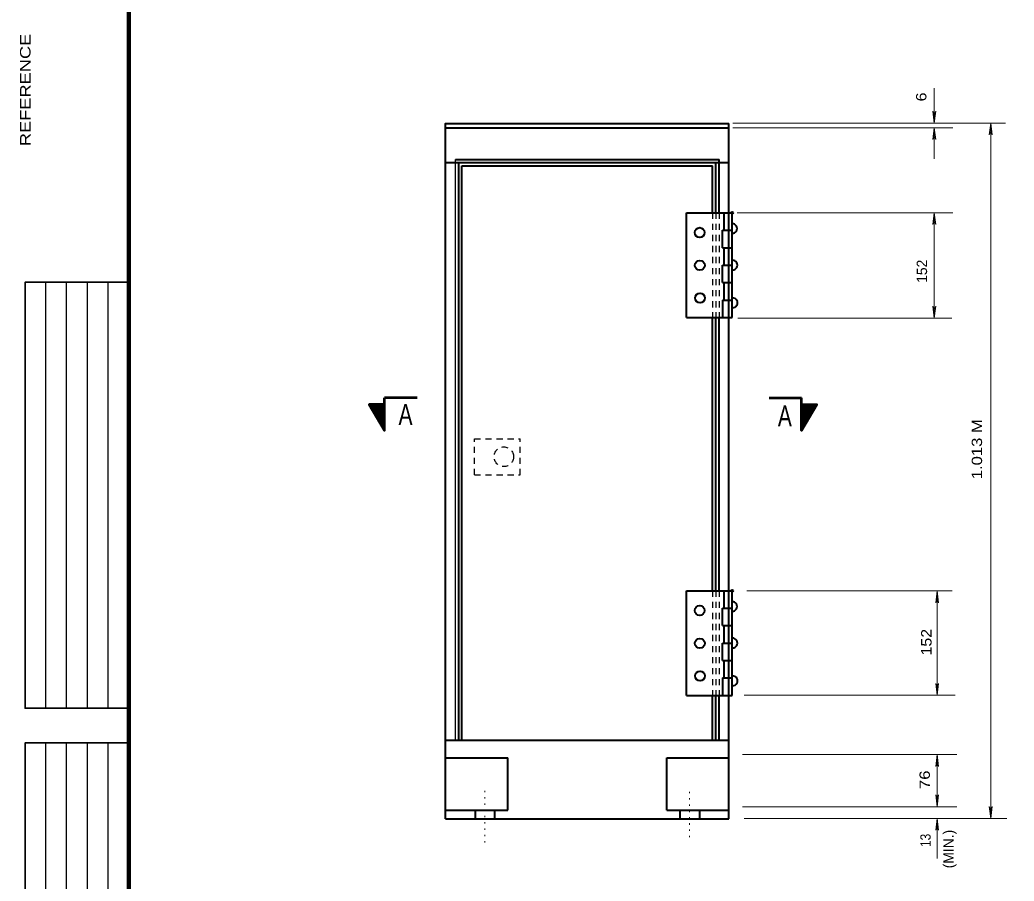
# Model space of a CAD drawing. Extents: x 312583 to 312853, y 144420 to 144585.
# Drawn here: x 312608.5 to 312681.4, y 144478 to 144541.1 of the extents above; entities that cross this region are included whole.
import ezdxf
from ezdxf.enums import TextEntityAlignment as Align

# ---------------------------------------------------------------- set-up
doc = ezdxf.new("R2010")
doc.units = 0
doc.header["$LTSCALE"] = 0.3
doc.header["$PDMODE"] = 32
doc.header["$PDSIZE"] = 0.15
doc.linetypes.add('DOTTED', pattern=[1.5, 0.3, -1.2])
doc.linetypes.add('SHORT_DASHED', pattern=[2.7, 1.5, -1.2])
doc.layers.add('1', color=7, linetype='Continuous', lineweight=40)
doc.layers.add('2', color=7, linetype='Continuous', lineweight=13)

msp = doc.modelspace()

# ---------------------------------------------------------------- linework, layer by layer
at = {"layer": '1'}
for p, q in [((312657.3797, 144526.9721), (312660.7377, 144526.9721)), ((312657.3797, 144519.3055), (312657.3797, 144526.9721)), ((312660.1397, 144525.6918), (312660.1397, 144526.9721)), ((312660.7377, 144519.3055), (312660.7377, 144526.9721)), ((312660.017, 144524.4115), (312660.017, 144525.6918)), ((312660.017, 144525.6918), (312660.7377, 144525.6918)), ((312660.017, 144524.4115), (312660.7377, 144524.4115)), ((312660.1397, 144523.1388), (312660.1397, 144524.4115)), ((312660.017, 144521.8585), (312660.017, 144523.1388)), ((312660.017, 144523.1388), (312660.7377, 144523.1388)), ((312660.017, 144521.8585), (312660.7377, 144521.8585)), ((312660.1397, 144520.5781), (312660.1397, 144521.8585)), ((312660.017, 144520.5781), (312660.017, 144519.3055)), ((312660.017, 144520.5781), (312660.7377, 144520.5781)), ((312657.3797, 144519.3055), (312660.7377, 144519.3055)), ((312657.3797, 144499.2725), (312660.7377, 144499.2725)), ((312657.3797, 144491.6058), (312657.3797, 144499.2725)), ((312660.1397, 144497.9998), (312660.1397, 144499.2725)), ((312660.7377, 144491.6058), (312660.7377, 144499.2725)), ((312660.017, 144496.7195), (312660.017, 144497.9998)), ((312660.017, 144497.9998), (312660.7377, 144497.9998)), ((312660.017, 144496.7195), (312660.7377, 144496.7195)), ((312660.1397, 144495.4391), (312660.1397, 144496.7195)), ((312660.017, 144494.1665), (312660.017, 144495.4391)), ((312660.017, 144495.4391), (312660.7377, 144495.4391)), ((312660.017, 144494.1665), (312660.7377, 144494.1665)), ((312660.1397, 144492.8861), (312660.1397, 144494.1665)), ((312660.017, 144492.8861), (312660.017, 144491.6058)), ((312660.017, 144492.8861), (312660.7377, 144492.8861)), ((312657.3797, 144491.6058), (312660.7377, 144491.6058))]:
    msp.add_line(p, q, dxfattribs=at)
at = {"layer": '1', "linetype": 'SHORT_DASHED', "lineweight": 25}
for p, q in [((312659.2887, 144526.9721), (312659.2887, 144519.3055)), ((312659.534, 144526.9721), (312659.534, 144519.3055)), ((312659.7717, 144526.9721), (312659.7717, 144519.2441)), ((312659.2887, 144499.2725), (312659.2887, 144491.6058)), ((312659.534, 144499.2725), (312659.534, 144491.6058)), ((312659.7717, 144499.2725), (312659.7717, 144491.5445))]:
    msp.add_line(p, q, dxfattribs=at)
at = {"layer": '1', "lineweight": 25}
for p, q in [((312610.4087, 144490.6573), (312610.4087, 144521.8756)), ((312611.9315, 144490.6573), (312611.9315, 144521.8756)), ((312613.4543, 144490.6573), (312613.4543, 144521.8756)), ((312614.9772, 144490.6573), (312614.9772, 144521.8756)), ((312610.4087, 144456.901), (312610.4087, 144488.1192)), ((312611.9315, 144456.901), (312611.9315, 144488.1192)), ((312613.4543, 144456.901), (312613.4543, 144488.1192)), ((312614.9772, 144456.901), (312614.9772, 144488.1192))]:
    msp.add_line(p, q, dxfattribs=at)
at = {"layer": '1', "lineweight": 53}
for p, q in [((312637.6303, 144513.4021), (312635.2383, 144513.4021)), ((312635.2383, 144512.9268), (312635.2383, 144513.4021)), ((312663.4363, 144513.4021), (312665.8283, 144513.4021)), ((312665.8283, 144512.9268), (312665.8283, 144513.4021))]:
    msp.add_line(p, q, dxfattribs=at)
at = {"layer": '1', "lineweight": 35}
for p, q in [((312634.1573, 144512.9268), (312634.142, 144512.9115)), ((312634.2033, 144512.9268), (312634.1497, 144512.8885)), ((312634.257, 144512.9268), (312634.165, 144512.8731)), ((312634.303, 144512.9268), (312634.1803, 144512.8501)), ((312634.3567, 144512.9268), (312634.188, 144512.8271)), ((312634.395, 144512.9268), (312634.2033, 144512.8118)), ((312634.4487, 144512.9268), (312634.211, 144512.7888)), ((312634.4947, 144512.9268), (312634.2263, 144512.7658)), ((312634.5407, 144512.9268), (312634.234, 144512.7505)), ((312634.5867, 144512.9268), (312634.2493, 144512.7198)), ((312634.6403, 144512.9268), (312634.257, 144512.7045)), ((312634.6863, 144512.9268), (312634.2723, 144512.6815)), ((312634.7323, 144512.9268), (312634.28, 144512.6585)), ((312634.786, 144512.9268), (312634.2953, 144512.6431)), ((312634.832, 144512.9268), (312634.303, 144512.6201)), ((312634.878, 144512.9268), (312634.3183, 144512.6048)), ((312634.9317, 144512.9268), (312634.3337, 144512.5818)), ((312634.9777, 144512.9268), (312634.3413, 144512.5588)), ((312635.0237, 144512.9268), (312634.3567, 144512.5435)), ((312635.0697, 144512.9268), (312634.372, 144512.5205)), ((312635.1233, 144512.9268), (312634.3797, 144512.4975)), ((312635.1617, 144512.9268), (312634.395, 144512.4821)), ((312635.2153, 144512.9268), (312634.4027, 144512.4515)), ((312635.2383, 144512.9115), (312634.418, 144512.4361)), ((312635.2383, 144512.8808), (312634.4257, 144512.4131)), ((312635.2383, 144512.8501), (312634.441, 144512.3901)), ((312635.2383, 144512.8271), (312634.4487, 144512.3748)), ((312635.2383, 144512.7965), (312634.464, 144512.3518)), ((312635.2307, 144512.7735), (312634.4717, 144512.3288)), ((312635.2307, 144512.7428), (312634.487, 144512.3135)), ((312635.2383, 144512.7198), (312634.4947, 144512.2905)), ((312635.2383, 144512.6891), (312634.51, 144512.2675)), ((312635.2383, 144512.6585), (312634.5253, 144512.2521)), ((312665.8283, 144512.9115), (312666.6487, 144512.4361)), ((312665.8283, 144512.8808), (312666.641, 144512.4131)), ((312665.8283, 144512.8501), (312666.6257, 144512.3901)), ((312665.8283, 144512.8271), (312666.618, 144512.3748)), ((312665.8283, 144512.7965), (312666.6027, 144512.3518)), ((312665.8283, 144512.7198), (312666.572, 144512.2905)), ((312665.8283, 144512.6891), (312666.5567, 144512.2675)), ((312665.8283, 144512.6585), (312666.5413, 144512.2521)), ((312665.836, 144512.7735), (312666.595, 144512.3288)), ((312665.836, 144512.7428), (312666.5797, 144512.3135)), ((312665.8513, 144512.9268), (312666.664, 144512.4515)), ((312665.905, 144512.9268), (312666.6717, 144512.4821)), ((312665.9433, 144512.9268), (312666.687, 144512.4975)), ((312665.997, 144512.9268), (312666.6947, 144512.5205)), ((312666.043, 144512.9268), (312666.71, 144512.5435)), ((312666.089, 144512.9268), (312666.7253, 144512.5588)), ((312666.135, 144512.9268), (312666.733, 144512.5818)), ((312666.1887, 144512.9268), (312666.7483, 144512.6048)), ((312666.2347, 144512.9268), (312666.7637, 144512.6201)), ((312666.2807, 144512.9268), (312666.7713, 144512.6431)), ((312666.3343, 144512.9268), (312666.7867, 144512.6585)), ((312666.3803, 144512.9268), (312666.7943, 144512.6815)), ((312666.4263, 144512.9268), (312666.8097, 144512.7045)), ((312666.48, 144512.9268), (312666.8173, 144512.7198)), ((312666.526, 144512.9268), (312666.8327, 144512.7505)), ((312666.572, 144512.9268), (312666.8403, 144512.7658)), ((312666.618, 144512.9268), (312666.8557, 144512.7888)), ((312666.6717, 144512.9268), (312666.8633, 144512.8118)), ((312666.71, 144512.9268), (312666.8787, 144512.8271)), ((312666.7637, 144512.9268), (312666.8863, 144512.8501)), ((312666.8097, 144512.9268), (312666.9017, 144512.8731)), ((312666.8633, 144512.9268), (312666.917, 144512.8885)), ((312666.9093, 144512.9268), (312666.9247, 144512.9115)), ((312635.2383, 144512.6355), (312634.533, 144512.2291)), ((312635.2383, 144512.6048), (312634.5483, 144512.2061)), ((312635.2383, 144512.5741), (312634.5637, 144512.1831)), ((312635.2383, 144512.5511), (312634.5713, 144512.1678)), ((312635.2307, 144512.5205), (312634.5867, 144512.1448)), ((312635.2383, 144512.4898), (312634.5943, 144512.1218)), ((312635.2383, 144512.4668), (312634.6097, 144512.1065)), ((312635.2383, 144512.4438), (312634.6173, 144512.0835)), ((312635.2383, 144512.4131), (312634.6327, 144512.0605)), ((312635.2383, 144512.3825), (312634.6403, 144512.0451)), ((312635.2383, 144512.3518), (312634.6557, 144512.0221)), ((312635.2383, 144512.3288), (312634.6633, 144511.9991)), ((312635.2383, 144512.2981), (312634.6787, 144511.9838)), ((312635.2307, 144512.2751), (312634.6863, 144511.9531)), ((312635.2383, 144512.2445), (312634.7017, 144511.9378)), ((312635.2383, 144512.2215), (312634.717, 144511.9148)), ((312635.2383, 144512.1908), (312634.7247, 144511.8918)), ((312635.2383, 144512.1601), (312634.74, 144511.8765)), ((312635.2383, 144512.1371), (312634.7477, 144511.8535)), ((312635.2383, 144512.1065), (312634.763, 144511.8305)), ((312635.2383, 144512.0758), (312634.7707, 144511.8151)), ((312635.2383, 144512.0528), (312634.786, 144511.7921)), ((312635.2383, 144512.0221), (312634.7937, 144511.7691)), ((312635.2383, 144511.9915), (312634.809, 144511.7538)), ((312635.2383, 144511.9685), (312634.8167, 144511.7308)), ((312635.2383, 144511.9455), (312634.832, 144511.7078)), ((312665.8283, 144512.6355), (312666.5337, 144512.2291)), ((312665.8283, 144512.6048), (312666.5183, 144512.2061)), ((312665.8283, 144512.5741), (312666.503, 144512.1831)), ((312665.8283, 144512.5511), (312666.4953, 144512.1678)), ((312665.8283, 144512.4898), (312666.4723, 144512.1218)), ((312665.8283, 144512.4668), (312666.457, 144512.1065)), ((312665.8283, 144512.4438), (312666.4493, 144512.0835)), ((312665.8283, 144512.4131), (312666.434, 144512.0605)), ((312665.8283, 144512.3825), (312666.4263, 144512.0451)), ((312665.8283, 144512.3518), (312666.411, 144512.0221)), ((312665.8283, 144512.3288), (312666.4033, 144511.9991)), ((312665.8283, 144512.2981), (312666.388, 144511.9838)), ((312665.8283, 144512.2445), (312666.365, 144511.9378)), ((312665.8283, 144512.2215), (312666.3497, 144511.9148)), ((312665.8283, 144512.1908), (312666.342, 144511.8918)), ((312665.8283, 144512.1601), (312666.3267, 144511.8765)), ((312665.8283, 144512.1371), (312666.319, 144511.8535)), ((312665.8283, 144512.1065), (312666.3037, 144511.8305)), ((312665.8283, 144512.0758), (312666.296, 144511.8151)), ((312665.8283, 144512.0528), (312666.2807, 144511.7921)), ((312665.8283, 144512.0221), (312666.273, 144511.7691)), ((312665.8283, 144511.9915), (312666.2577, 144511.7538)), ((312665.8283, 144511.9685), (312666.25, 144511.7308)), ((312665.8283, 144511.9455), (312666.2347, 144511.7078)), ((312665.836, 144512.5205), (312666.48, 144512.1448)), ((312665.836, 144512.2751), (312666.3803, 144511.9531)), ((312635.2383, 144511.9148), (312634.8397, 144511.6848)), ((312635.2383, 144511.8841), (312634.855, 144511.6695)), ((312635.2383, 144511.8535), (312634.8703, 144511.6465)), ((312635.2383, 144511.8305), (312634.878, 144511.6235)), ((312635.2383, 144511.7998), (312634.8933, 144511.6081)), ((312635.2383, 144511.7768), (312634.9087, 144511.5851)), ((312635.2383, 144511.7461), (312634.9163, 144511.5621)), ((312635.2383, 144511.7231), (312634.9317, 144511.5468)), ((312635.2383, 144511.6925), (312634.9393, 144511.5238)), ((312635.2383, 144511.6618), (312634.9547, 144511.5008)), ((312635.2383, 144511.6388), (312634.9623, 144511.4855)), ((312635.2383, 144511.6081), (312634.9777, 144511.4548)), ((312635.2383, 144511.5851), (312634.9853, 144511.4395)), ((312635.2383, 144511.5545), (312635.0007, 144511.4165)), ((312635.2383, 144511.5238), (312635.0083, 144511.3935)), ((312635.2383, 144511.5008), (312635.0237, 144511.3781)), ((312635.2383, 144511.4701), (312635.0313, 144511.3551)), ((312635.2383, 144511.4471), (312635.0467, 144511.3321)), ((312635.2383, 144511.4165), (312635.062, 144511.3168)), ((312635.2383, 144511.3858), (312635.0697, 144511.2938)), ((312635.2383, 144511.3551), (312635.085, 144511.2708)), ((312635.2383, 144511.3321), (312635.1003, 144511.2555)), ((312635.2383, 144511.3015), (312635.108, 144511.2325)), ((312635.2383, 144511.2785), (312635.1233, 144511.2095)), ((312635.2383, 144511.2555), (312635.131, 144511.1865)), ((312635.2383, 144511.2248), (312635.1463, 144511.1711)), ((312665.8283, 144511.9148), (312666.227, 144511.6848)), ((312665.8283, 144511.8841), (312666.2117, 144511.6695)), ((312665.8283, 144511.8535), (312666.1963, 144511.6465)), ((312665.8283, 144511.8305), (312666.1887, 144511.6235)), ((312665.8283, 144511.7998), (312666.1733, 144511.6081)), ((312665.8283, 144511.7768), (312666.158, 144511.5851)), ((312665.8283, 144511.7461), (312666.1503, 144511.5621)), ((312665.8283, 144511.7231), (312666.135, 144511.5468)), ((312665.8283, 144511.6925), (312666.1273, 144511.5238)), ((312665.8283, 144511.6618), (312666.112, 144511.5008)), ((312665.8283, 144511.6388), (312666.1043, 144511.4855)), ((312665.8283, 144511.6081), (312666.089, 144511.4548)), ((312665.8283, 144511.5851), (312666.0813, 144511.4395)), ((312665.8283, 144511.5545), (312666.066, 144511.4165)), ((312665.8283, 144511.5238), (312666.0583, 144511.3935)), ((312665.8283, 144511.5008), (312666.043, 144511.3781)), ((312665.8283, 144511.4701), (312666.0353, 144511.3551)), ((312665.8283, 144511.4471), (312666.02, 144511.3321)), ((312665.8283, 144511.4165), (312666.0047, 144511.3168)), ((312665.8283, 144511.3858), (312665.997, 144511.2938)), ((312665.8283, 144511.3551), (312665.9817, 144511.2708)), ((312665.8283, 144511.3321), (312665.9663, 144511.2555)), ((312665.8283, 144511.3015), (312665.9587, 144511.2325)), ((312665.8283, 144511.2785), (312665.9433, 144511.2095)), ((312665.8283, 144511.2555), (312665.9357, 144511.1865)), ((312665.8283, 144511.2248), (312665.9203, 144511.1711)), ((312635.2383, 144511.1941), (312635.154, 144511.1481)), ((312635.2383, 144511.1635), (312635.1693, 144511.1251)), ((312635.2383, 144511.1405), (312635.177, 144511.1098)), ((312635.2383, 144511.1098), (312635.1923, 144511.0868)), ((312635.2383, 144511.0868), (312635.2, 144511.0638)), ((312635.2383, 144511.0561), (312635.2153, 144511.0485)), ((312635.2383, 144511.0255), (312635.223, 144511.0255)), ((312665.8283, 144511.1941), (312665.9127, 144511.1481)), ((312665.8283, 144511.1635), (312665.8973, 144511.1251)), ((312665.8283, 144511.1405), (312665.8897, 144511.1098)), ((312665.8283, 144511.1098), (312665.8743, 144511.0868)), ((312665.8283, 144511.0868), (312665.8667, 144511.0638)), ((312665.8283, 144511.0561), (312665.8513, 144511.0485)), ((312665.8283, 144511.0255), (312665.8437, 144511.0255))]:
    msp.add_line(p, q, dxfattribs=at)
at = {"layer": '1', "lineweight": 158}
msp.add_lwpolyline([(312616.5, 144423.1446), (312616.5, 144585.0846), (312849, 144585.0846)], dxfattribs=at)
at = {"layer": '1', "lineweight": 35}
for points in [[(312616.5, 144490.6573), (312608.8858, 144490.6573), (312608.8858, 144521.8756), (312616.5, 144521.8756)], [(312616.5, 144456.901), (312608.8858, 144456.901), (312608.8858, 144488.1192), (312616.5, 144488.1192)]]:
    msp.add_lwpolyline(points, dxfattribs=at)
at = {"layer": '1', "lineweight": 53}
for points in [[(312635.2383, 144512.9268), (312634.1267, 144512.9268), (312635.2383, 144511.0101)], [(312665.8283, 144512.9268), (312666.94, 144512.9268), (312665.8283, 144511.0101)]]:
    msp.add_lwpolyline(points, close=True, dxfattribs=at)
at = {"layer": '1', "linetype": 'SHORT_DASHED', "lineweight": 25}
for points in [[(312641.8393, 144507.7595), (312645.1973, 144507.7595), (312645.1973, 144510.3968)], [(312641.8393, 144507.7595), (312641.8393, 144510.3968), (312645.1973, 144510.3968)]]:
    msp.add_lwpolyline(points, dxfattribs=at)
at = {"layer": '1'}
for centre in [(312658.3521, 144525.5219), (312658.3648, 144523.1184), (312658.3776, 144520.7276), (312658.3521, 144497.8273), (312658.3648, 144495.4238), (312658.3776, 144493.0331)]:
    msp.add_circle(centre, 0.3594, dxfattribs=at)
at = {"layer": '1', "linetype": 'SHORT_DASHED', "lineweight": 25}
msp.add_circle((312643.9937, 144509.0935), 0.7188, dxfattribs=at)
at = {"layer": '1'}
for centre in [(312660.73, 144525.817), (312660.7568, 144523.1337), (312660.7696, 144520.3711), (312660.73, 144498.1225), (312660.7568, 144495.4391), (312660.7696, 144492.6766)]:
    msp.add_arc(centre, 0.3594, 269.38833, 90.61386, dxfattribs=at)
for p in [(312660.7377, 144526.9721), (312660.7377, 144499.2725)]:
    msp.add_point(p, dxfattribs=at)
at = {"layer": '2'}
for p, q in [((312675.5497, 144533.5425), (312675.5497, 144536.1155)), ((312675.4423, 144534.4088), (312675.5497, 144534.1328)), ((312675.5497, 144533.5425), (312675.4423, 144534.4088)), ((312675.657, 144534.4088), (312675.5497, 144534.1328)), ((312675.5497, 144533.5425), (312675.657, 144534.4088)), ((312660.776, 144533.5425), (312680.7783, 144533.5425)), ((312660.776, 144533.1975), (312676.9067, 144533.1975)), ((312675.5497, 144533.1975), (312675.4423, 144532.3311)), ((312675.5497, 144530.9358), (312675.5497, 144533.1975)), ((312675.5497, 144533.1975), (312675.657, 144532.3311)), ((312679.6973, 144533.5425), (312679.59, 144532.6761)), ((312679.6973, 144482.5898), (312679.6973, 144533.5425)), ((312679.6973, 144533.5425), (312679.8047, 144532.6761)), ((312675.4423, 144532.3311), (312675.5497, 144532.6071)), ((312675.657, 144532.3311), (312675.5497, 144532.6071)), ((312679.59, 144532.6761), (312679.6973, 144532.9521)), ((312679.8047, 144532.6761), (312679.6973, 144532.9521)), ((312661.098, 144526.9798), (312676.9067, 144526.9798)), ((312675.5497, 144526.9798), (312675.4423, 144526.1135)), ((312675.5497, 144519.2595), (312675.5497, 144526.9798)), ((312675.5497, 144526.9798), (312675.657, 144526.1135)), ((312675.4423, 144526.1135), (312675.5497, 144526.3895)), ((312675.657, 144526.1135), (312675.5497, 144526.3895)), ((312675.4423, 144520.1258), (312675.5497, 144519.8498)), ((312675.5497, 144519.2595), (312675.4423, 144520.1258)), ((312675.657, 144520.1258), (312675.5497, 144519.8498)), ((312675.5497, 144519.2595), (312675.657, 144520.1258)), ((312661.1517, 144519.2595), (312676.853, 144519.2595)), ((312661.811, 144499.2648), (312676.876, 144499.2648)), ((312675.7643, 144499.2648), (312675.657, 144498.3985)), ((312675.7643, 144491.6211), (312675.7643, 144499.2648)), ((312675.7643, 144499.2648), (312675.8717, 144498.3985)), ((312675.657, 144498.3985), (312675.7643, 144498.6745)), ((312675.8717, 144498.3985), (312675.7643, 144498.6745)), ((312675.657, 144492.4875), (312675.7643, 144492.2115)), ((312675.7643, 144491.6211), (312675.657, 144492.4875)), ((312675.8717, 144492.4875), (312675.7643, 144492.2115)), ((312675.7643, 144491.6211), (312675.8717, 144492.4875)), ((312661.604, 144491.6211), (312677.0907, 144491.6211)), ((312661.4967, 144487.2665), (312677.198, 144487.2665)), ((312675.7643, 144487.2665), (312675.657, 144486.4001)), ((312675.7643, 144483.4408), (312675.7643, 144487.2665)), ((312675.7643, 144487.2665), (312675.8717, 144486.4001)), ((312675.657, 144486.4001), (312675.7643, 144486.6761)), ((312675.8717, 144486.4001), (312675.7643, 144486.6761)), ((312675.657, 144484.3071), (312675.7643, 144484.0311)), ((312675.7643, 144483.4408), (312675.657, 144484.3071)), ((312675.8717, 144484.3071), (312675.7643, 144484.0311)), ((312675.7643, 144483.4408), (312675.8717, 144484.3071)), ((312661.4967, 144483.4408), (312677.198, 144483.4408)), ((312679.59, 144483.4561), (312679.6973, 144483.1801)), ((312679.6973, 144482.5898), (312679.59, 144483.4561)), ((312679.8047, 144483.4561), (312679.6973, 144483.1801)), ((312679.6973, 144482.5898), (312679.8047, 144483.4561)), ((312661.604, 144482.5898), (312680.8857, 144482.5898)), ((312675.7643, 144482.5898), (312675.657, 144481.7235)), ((312675.7643, 144482.5898), (312675.8717, 144481.7235)), ((312675.7643, 144479.6535), (312675.7643, 144482.5898)), ((312675.657, 144481.7235), (312675.7643, 144481.9995)), ((312675.8717, 144481.7235), (312675.7643, 144481.9995))]:
    msp.add_line(p, q, dxfattribs=at)
at = {"layer": '2', "lineweight": 40}
for p, q in [((312639.7233, 144533.5195), (312660.4923, 144533.5195)), ((312639.7233, 144533.5195), (312660.4923, 144533.5195)), ((312639.7233, 144533.1975), (312660.4923, 144533.1975)), ((312660.4923, 144482.5668), (312660.4923, 144533.5195)), ((312639.7233, 144530.6445), (312660.4923, 144530.6445)), ((312640.444, 144530.8821), (312659.7717, 144530.8821)), ((312640.6817, 144488.3168), (312640.6817, 144530.6445)), ((312640.9193, 144488.3168), (312640.9193, 144530.4068)), ((312640.9193, 144530.4068), (312659.2887, 144530.4068)), ((312659.2887, 144526.9721), (312659.2887, 144530.4068)), ((312659.534, 144526.9721), (312659.534, 144530.6445)), ((312659.7717, 144526.9721), (312659.7717, 144530.8821)), ((312659.2887, 144499.2725), (312659.2887, 144519.3055)), ((312659.534, 144499.2725), (312659.534, 144519.3055)), ((312659.7717, 144499.2725), (312659.7717, 144519.3055)), ((312659.2887, 144488.3168), (312659.2887, 144491.6058)), ((312659.534, 144488.3168), (312659.534, 144491.6058)), ((312659.7717, 144488.3168), (312659.7717, 144491.6058)), ((312639.7233, 144488.3168), (312660.4923, 144488.3168)), ((312639.7233, 144487.0365), (312644.2773, 144487.0365)), ((312644.2773, 144483.2031), (312644.2773, 144487.0365)), ((312655.9383, 144483.2031), (312655.9383, 144487.0365)), ((312655.9383, 144487.0365), (312660.4923, 144487.0365)), ((312639.7233, 144483.2031), (312644.2773, 144483.2031)), ((312641.8777, 144483.2031), (312641.8777, 144482.5668)), ((312643.319, 144483.2031), (312643.319, 144482.5668)), ((312655.9383, 144483.2031), (312660.4923, 144483.2031)), ((312656.8967, 144483.2031), (312656.8967, 144482.5668)), ((312658.3303, 144483.2031), (312658.3303, 144482.5668)), ((312639.7233, 144482.5668), (312660.4923, 144482.5668))]:
    msp.add_line(p, q, dxfattribs=at)
at = {"layer": '2', "lineweight": 25}
msp.add_line((312640.444, 144488.3168), (312640.444, 144530.8821), dxfattribs=at)
at = {"layer": '2', "linetype": 'DOTTED'}
for p, q in [((312642.5983, 144480.8341), (312642.5983, 144484.9281)), ((312657.6173, 144481.2098), (312657.6173, 144484.8745))]:
    msp.add_line(p, q, dxfattribs=at)
at = {"layer": '2', "lineweight": 40}
msp.add_lwpolyline([(312639.7233, 144482.5668), (312639.7233, 144533.5195), (312660.4923, 144533.5195)], dxfattribs=at)

# ---------------------------------------------------------------- texts
at = {"layer": '1', "width": 1.3}
msp.add_text('REFERENCE                                                              ', height=0.7682, rotation=90, dxfattribs=at).set_placement((312609.2854, 144531.8549))
at = {"layer": '1', "width": 0.75}
for p in [(312636.7832, 144511.4241), (312664.5978, 144511.3168)]:
    msp.add_text('A', height=1.533, dxfattribs=at).set_placement(p, align=Align.CENTER)
at = {"layer": '2'}
for s, width, p in [('6 ', 1.15, (312674.9769, 144535.1348)), ('1.013 M', 1.2, (312679.0599, 144507.4427)), ('152 ', 1.15, (312675.3526, 144494.528)), ('76 ', 1.2, (312675.231, 144484.7436)), ('13', 0.85, (312675.2921, 144480.5016))]:
    msp.add_text(s, height=0.76, rotation=90, dxfattribs=dict(at, width=width)).set_placement(p)
for s, p in [('152', (312675.0285, 144521.8376)), ('(MIN.)', (312676.9747, 144478.9345))]:
    msp.add_text(s, height=0.76, rotation=90, dxfattribs=at).set_placement(p)

doc.saveas('drawing.dxf')
